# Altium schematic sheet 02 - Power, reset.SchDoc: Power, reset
size A3; PageSetup: Record=PageOptions¦CenterHorizontal=True¦CenterVertical=True¦PrintScale=0.70¦XCorrection=1.00¦YCorrection=1.00¦PrintKind=0¦BorderSize=5000000¦LeftOffset=0¦BottomOffset=0¦Orientation=2¦PaperLength=4200¦PaperWidth=2970¦Scale=100¦PaperSource=7¦PrintQuality=600¦MediaType=1¦DitherType=10¦PaperKind=A4¦PrintScaleMode=1; Author: Juan Anzola; SheetNumber: 2; SheetTotal: 20
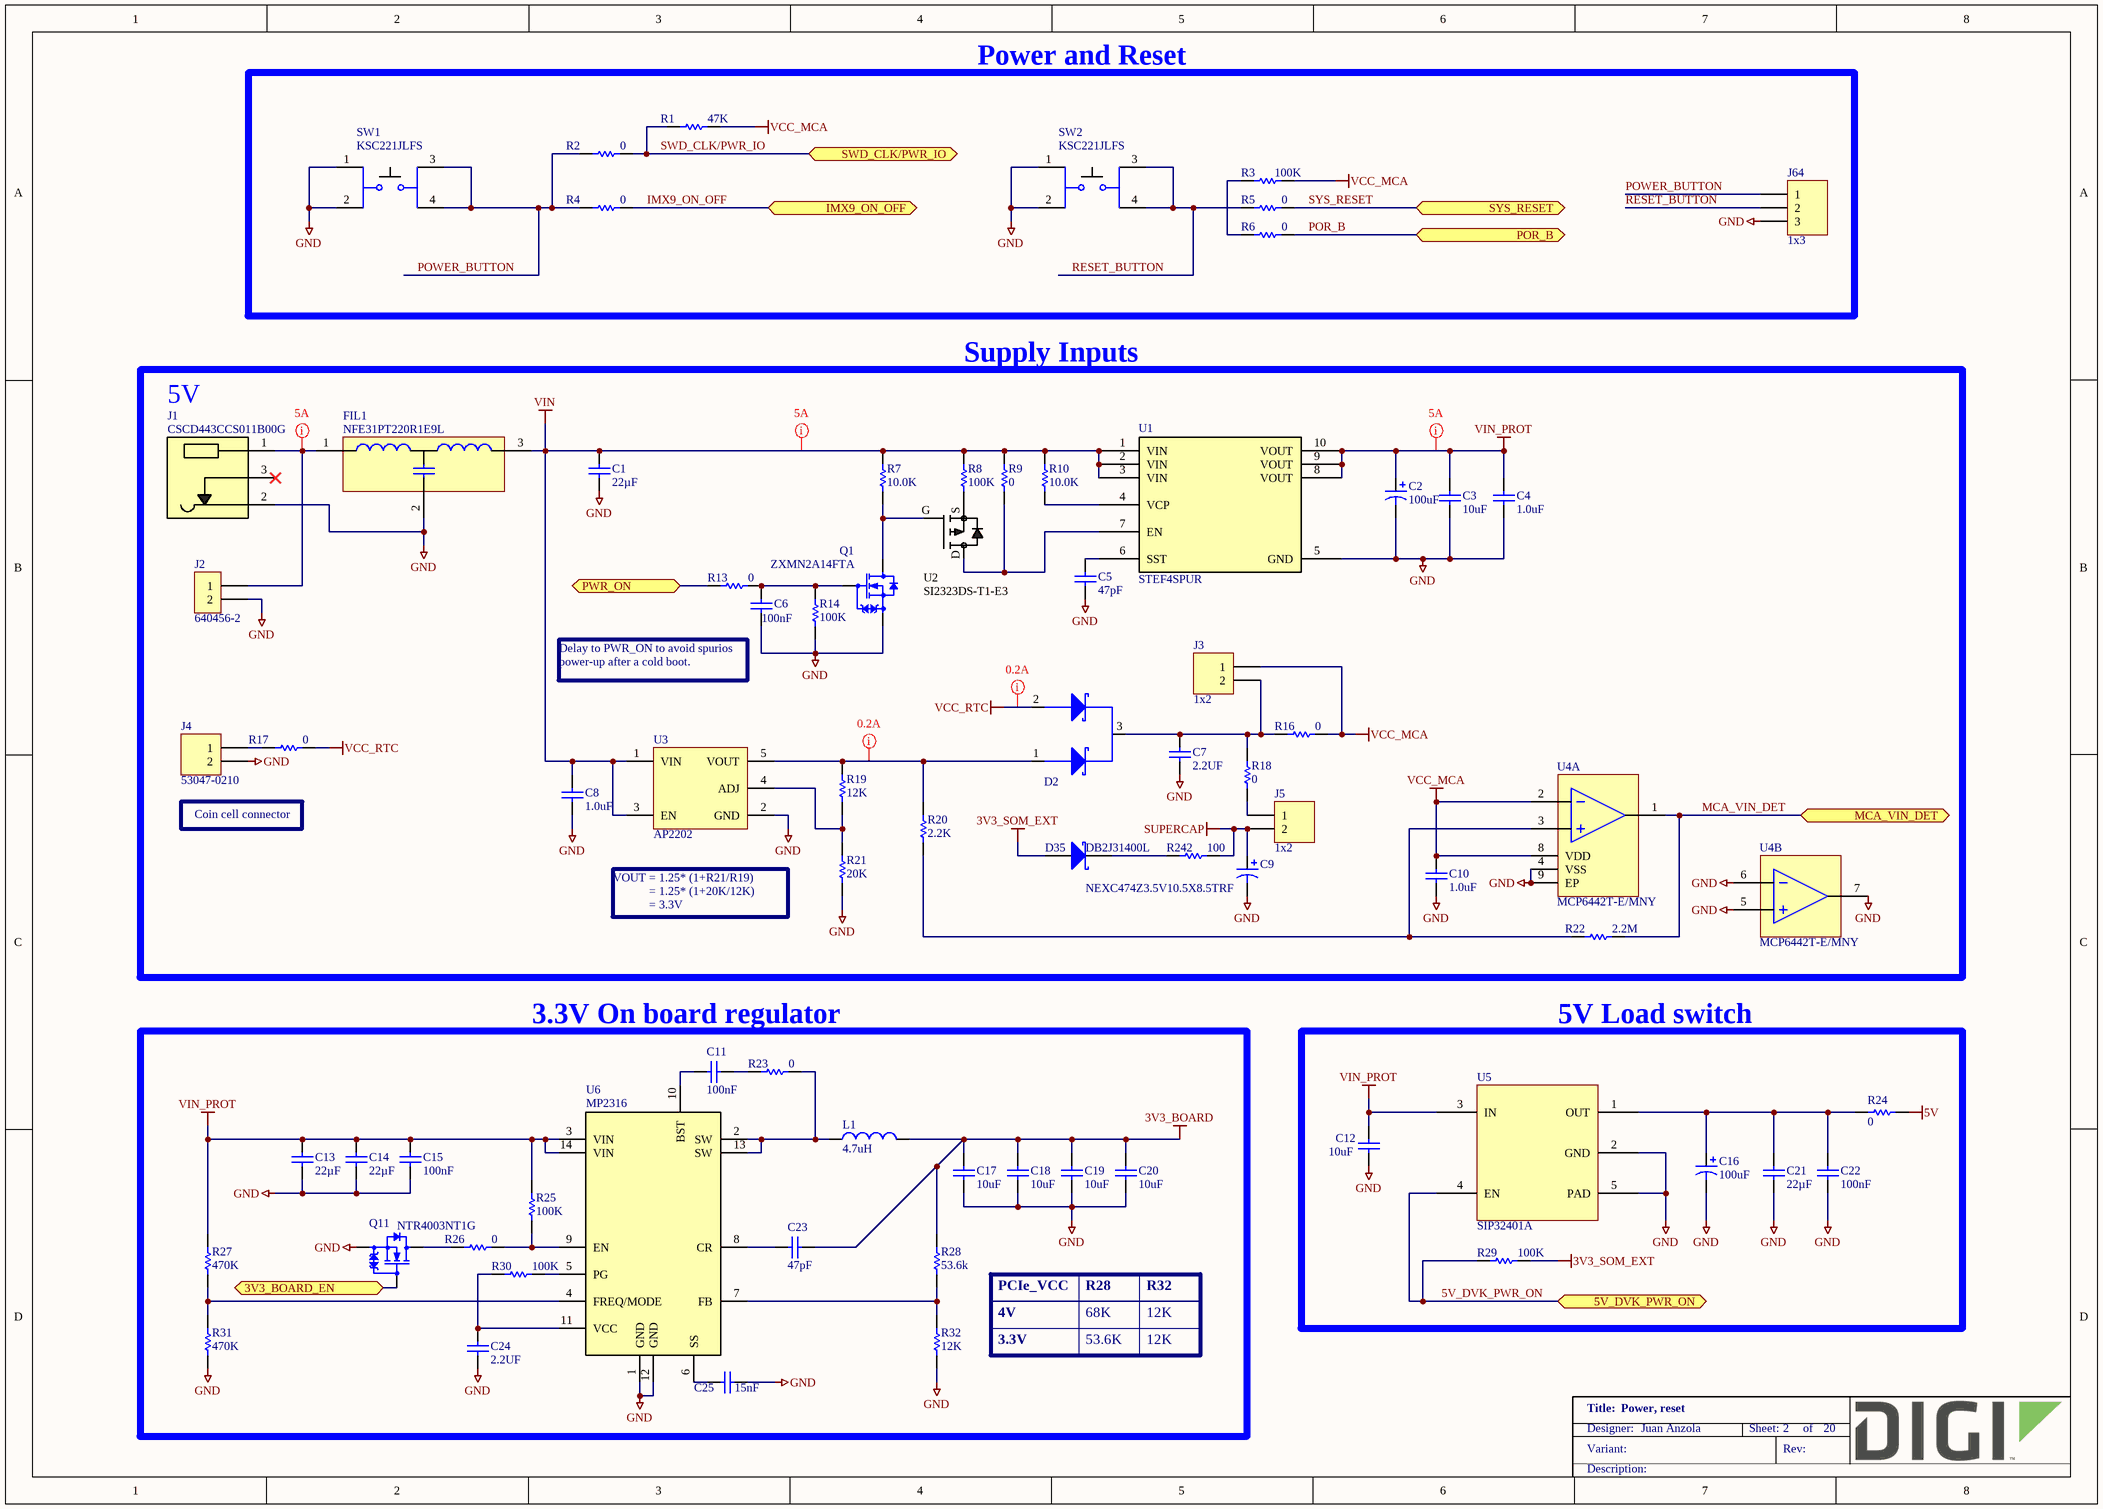
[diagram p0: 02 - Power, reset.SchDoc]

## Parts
C1  22µF  [CAPC1608X90N]
C2  100uF  [CAPMP3216X120N]
C3  10uF  [CAPC1005X55N]
C4  1.0uF  [CAPC1005X55N]
C5  47pF  [CAPC1005X55N]
C6  100nF  [CAPC1005X55N]
C7  2.2UF  [CAPC1608X90N]
C8  1.0uF  [CAPC1005X55N]
C9  NEXC474Z3.5V10.5X8.5TRF  [NEXC474Z3.5V10.5X8.5TRF]
C10  1.0uF  [CAPC1005X55N]
C11  100nF  [CAPC1005X55N]
C12  10uF  [CAPC1005X55N]
C13  22µF  [CAPC1608X90N]
C14  22µF  [CAPC1608X90N]
C15  100nF  [CAPC1005X55N]
C16  100uF  [CAPMP3216X120N]
C17  10uF  [CAPC2013X135N]
C18  10uF  [CAPC2013X135N]
C19  10uF  [CAPC2013X135N]
C20  10uF  [CAPC2013X135N]
C21  22µF  [CAPC1608X90N]
C22  100nF  [CAPC1005X55N]
C23  47pF  [CAPC1005X55N]
C24  2.2UF  [CAPC1608X90N]
C25  15nF  [CAPC1005X55N]
D2  BAT54CWT1G  [SOT65P210X100-3AN]  (value not drawn)
D35  DB2J31400L  [SODFL2513X80N]
FIL1  NFE31PT220R1E9L  [FIL_NFE31P]
J1  CSCD443CCS011B00G  [conn_CSCD443CCS011B00G]
J2  640456-2  [TE_640456-2]
J3  1x2  [FCI_68002-102HLF]
J4  Manufacturer_Part_Number: 53047-0210  [MOLEX_53047-0210_Flex]  (hidden comment: 1x2P)
J5  1x2  [FCI_68002-102HLF]
J64  1x3  [SAMTEC_TSW-103-07-G-S]
L1  4.7uH  [IND_DG6045C]
Q1  ZXMN2A14FTA  [SOT95P240X110_GSD-3N]
Q11  NTR4003NT1G  [SOT95P240X110_GSD-3N]
R1  47K  [RESC1005X40N]
R2  0  [RESC1005X40N]
R3  100K  [RESC1005X40N]
R4  0  [RESC1005X40N]
R5  0  [RESC1005X40N]
R6  0  [RESC1005X40N]
R7  10.0K  [RESC1005X40N]
R8  100K  [RESC1005X40N]
R9  0  [RESC1005X40N]
R10  10.0K  [RESC1005X40N]
R13  0  [RESC1005X40N]
R14  100K  [RESC1005X40N]
R16  0  [RESC1609X55N]
R17  0  [RESC1609X55N]
R18  0  [RESC1005X40N]
R19  12K  [RESC1609X55N]
R20  2.2K  [RESC1005X40N]
R21  20K  [RESC1609X55N]
R22  2.2M  [RESC0603X28N]
R23  0  [RESC1609X55N]
R24  0  [RESC1609X55N]
R25  100K  [RESC1005X40N]
R26  0  [RESC1005X40N]
R27  470K  [RESC1005X40N]
R28  53.6k  [RESC1609X55N]
R29  100K  [RESC1005X40N]
R30  100K  [RESC1005X40N]
R31  470K  [RESC1005X40N]
R32  12K  [RESC1609X55N]
R242  100  [RESC1005X40N]
SW1  KSC221JLFS  [SW_KSC221J]
SW2  KSC221JLFS  [SW_KSC221J]
U1  STEF4SPUR  [SON50P300X300X80-11T164X238N]
U2  SI2323DS-T1-E3  [SOT95P240X110_GSD-3N]
U3  AP2202  [SOT95P280X145-5N]
U4  MCP6442T-E/MNY  [SON50P300X200X80-9N]  (parts A,B of 2)
U5  SIP32401A  [SON50P120X160X60-5T55X91N]
U6  MP2316  [QFN_MPS_MP2316]

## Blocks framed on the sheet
Power and Reset: J64 R1-R6 SW1 SW2
Supply Inputs: C1-C10 D2 D35 FIL1 J1-J5 Q1 R7-R10 R13 R14 R16-R22 R242 U1-U4
3.3V On board regulator: C11 C13-C15 C17-C20 C23-C25 L1 Q11 R23 R25-R28 R30-R32 U6
5V Load switch: C12 C16 C21 C22 R24 R29 U5

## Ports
3V3_BOARD_EN (bidir), 5V_DVK_PWR_ON (bidir), IMX9_ON_OFF (bidir), MCA_VIN_DET (bidir), POR_B (bidir), PWR_ON (bidir), SWD_CLK/PWR_IO (bidir), SYS_RESET (bidir)

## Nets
3V3_BOARD: C17.2 C18.2 C19.2 C20.2 C23.2 L1.2 R28.2
3V3_SOM_EXT: D35.A R29.2
5V: R24.2
GND: C1.1 C2.2 C3.1 C4.1 C5.1 C6.2 C7.1 C8.1 C9.2 C10.2 C12.1 C13.1 C14.1 C15.1 C16.2 C17.1 C18.1 C19.1 C20.1 C21.1 C22.1 C24.1 C25.1 FIL1.2 J1.2 J2.2 J4.2 J64.3 Q1.S Q11.S R14.2 R21.1 R31.1 R32.1 SW1.1 SW1.2 SW2.1 SW2.2 U1.5(GND) U3.2(GND) U4.4(VSS) U4.5(VINB+) U4.6(VINB-) U4.7(VOUTB) U4.9(EP) U5.2(GND) U5.5(PAD) U6.1(GND) U6.12(GND)
SUPERCAP: C9.1 J5.2 R242.1
VCC_MCA: C10.1 J3.1 R1.2 R3.2 R16.2 U4.2(VIN-) U4.8(VDD)
VCC_RTC: D2.2 R17.2
VIN: C1.2 C8.2 FIL1.3(GND) R7.2 R8.2 R9.2 R10.2 U1.1(VIN) U1.2(VIN) U1.3(VIN) U3.1(VIN) U3.3(EN)
VIN_PROT: C2.1 C3.2 C4.2 C12.2 C13.2 C14.2 C15.2 R25.2 R27.2 U1.8(VOUT) U1.9(VOUT) U1.10(VOUT) U5.3(IN) U6.3(VIN) U6.14(VIN)
3V3_BOARD_EN: Q11.G ; port 3V3_BOARD_EN
5V_DVK_PWR_ON: R29.1 U5.4(EN) ; port 5V_DVK_PWR_ON
IMX9_ON_OFF: R4.2 ; port IMX9_ON_OFF
MCA_VIN_DET: R22.2 U4.1(VOUT) ; port MCA_VIN_DET
POR_B: R6.2 ; port POR_B
POWER_BUTTON: J64.1 R2.1 R4.1 SW1.3 SW1.4
PWR_ON: R13.1 ; port PWR_ON
RESET_BUTTON: J64.2 R5.1 SW2.3 SW2.4
SWD_CLK/PWR_IO: R1.1 R2.2 ; port SWD_CLK/PWR_IO
SYS_RESET: R5.2 ; port SYS_RESET
NetC5_2: C5.2 U1.6(SST)
NetC6_1: C6.1 Q1.G R13.2 R14.1
NetC7_2: C7.2 D2.3 J3.2 R16.1 R18.2
NetC11_1: C11.1 U6.10(BST)
NetC11_2: C11.2 R23.1
NetC16_1: C16.1 C21.2 C22.2 R24.1 U5.1(OUT)
NetC23_1: C23.1 U6.8(CR)
NetC24_2: C24.2 R30.1 U6.11(VCC)
NetC25_2: C25.2 U6.6(SS)
NetD2_1: D2.1 R19.2 R20.2 U3.5(VOUT)
NetD35_K: D35.K R242.2
NetFIL1_1: FIL1.1(GND) J1.1 J2.1
NetJ4_1: J4.1 R17.1
NetJ5_1: J5.1 R18.1
NetL1_1: L1.1 R23.2 U6.2(SW) U6.13(SW)
NetQ1_D: Q1.D R7.1 U2.G
NetQ11_D: Q11.D R26.1
NetR3_1: R3.1 R6.1
NetR8_1: R8.1 U2.S
NetR9_1: R9.1 U1.7(EN) U2.D
NetR10_1: R10.1 U1.4(VCP)
NetR19_1: R19.1 R21.2 U3.4(ADJ)
NetR20_1: R20.1 R22.1 U4.3(VIN+)
NetR25_1: R25.1 R26.2 U6.9(EN)
NetR27_1: R27.1 R31.2 U6.4(FREQ/MODE)
NetR28_1: R28.1 R32.2 U6.7(FB)
NetR30_2: R30.2 U6.5(PG)

Not connected (* = marked no-connect by the designer): J1 3*

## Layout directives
net class 0.2A: NetD2_1, VCC_RTC
net class 5A: NetFIL1_1, VIN, VIN_PROT

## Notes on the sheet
- 5V
- (near C6) Delay to PWR_ON to avoid spurios
  power-up after a cold boot.
- Coin cell connector
- VOUT = 1.25* (1+R21/R19)
  = 1.25* (1+20K/12K)
  = 3.3V
- PCIe_VCC
- 4V
- R28
- 68K
- R32
- 12K
- 3.3V
- 53.6K

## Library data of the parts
C1 = 1000998: CAP CER 22UF 10V 20% X5R 0603; Part_Type: Capacitor; Manufacturer: Samsung; Manufacturer_Part_Number: CL10A226MP8NUNE; Manufacturer_Alt_1: TDK Corporation; Manufacturer_Alt_1_Part_Number: C1608X5R1A226M080AC; Digi_PN: 14050684; Component_Life_Cycle_State: Reviewed; Area: 2,27; Tolerance: 20
C2 C16 = 1001196: CAP TANT 100UF 6.3V 20% 1206; Part_Type: Capacitor; Manufacturer: Rohm; Manufacturer_Part_Number: TCTAL0J107M8R; Digi_PN: 14050490; Component_Life_Cycle_State: Reviewed; Area: 8.01; Project: CCWMX6_SBC board
C3 C12 = 1001168: CAP CER 10UF 10V 20% X5R 0402; Part_Type: Capacitor; Manufacturer: Samsung; Manufacturer_Part_Number: CL05A106MP5NUNC; Digi_PN: 14050689; Component_Life_Cycle_State: Reviewed; Area: 0.95; Project: CCWMX6_SBC board
C4 = 1001167: CAP CER 1UF 10V 10% X5R 0402; Part_Type: Capacitor; Manufacturer: Murata; Manufacturer_Part_Number: GRM155R61A105KE15D; Digi_PN: 14050399; Component_Life_Cycle_State: Reviewed; Area: 0,95; Project: CCWMX6_SBC board
C5 = 1000007: CAP 47pF 50V 5% NP0 0402; Part_Type: Capacitor; Manufacturer: Murata; Manufacturer_Part_Number: GRM1555C1H470JA01D; Manufacturer_Alt_1: AVX Corporation; Manufacturer_Alt_1_Part_Number: 04025A470JAT2A; Note: 14050747 is Digi No. for GE WDNU; Digi_PN: 14050309; Component_Life_Cycle_State: CAD Reviewed; Area: 0,95; Temp_Coef: C0G, NP0
C6 C22 = 1000006: CAP 100nF 16V 10% X7R 0402; Part_Type: Capacitor; Manufacturer: Murata; Manufacturer_Part_Number: GRM155R71C104KA88D; Component_Life_Cycle_State: CAD Reviewed; Area: 0.95; Project: KITT; Tolerance: 10; Digi_PN: 14050552
C7 C24 = 1001303: CAP CER 2.2UF 16V 10% X5R 0603; Part_Type: Capacitor; Manufacturer: TDK Corporation; Manufacturer_Part_Number: C1608X5R1C225K080AB; Digi_PN: 14050730; Component_Life_Cycle_State: Reviewed; Area: 2,27; Project: Pinnacle
C8 C10 = 1001167: CAP CER 1UF 10V 10% X5R 0402; Part_Type: Capacitor; Manufacturer: Murata; Manufacturer_Part_Number: GRM155R61A105KE15D; Digi_PN: 14050399; Component_Life_Cycle_State: Reviewed; Area: 0,95
C9 = 1002775: SMCAP, 0.47F 3.5V SUPERCAP 8.5x10.5x10.8mm SMT; Part_Type: Capacitor; Manufacturer: NIC; Digi_PN: 14050629; Component_Life_Cycle_State: Pending
C11 C15 = 1000006: CAP 100nF 16V 10% X7R 0402; Part_Type: Capacitor; Manufacturer: Murata; Manufacturer_Part_Number: GRM155R71C104KA88D; Digi_PN: 14050552; Component_Life_Cycle_State: CAD Reviewed; Area: 0.95; Project: KITT; Tolerance: 10
C13 C14 C21 = 1000998: CAP CER 22UF 10V 20% X5R 0603; Part_Type: Capacitor; Manufacturer: Samsung; Manufacturer_Part_Number: CL10A226MP8NUNE; Manufacturer_Alt_1: TDK Corporation; Manufacturer_Alt_1_Part_Number: C1608X5R1A226M080AC; Digi_PN: 14050684; Component_Life_Cycle_State: Reviewed; Area: 2.27; Project: ConnectCore i.MX6 module; Tolerance: 20
C17-C20 = 1000111: CAP CER 10UF 16V 10% X5R 0805; Part_Type: Capacitor; Manufacturer: Murata; Manufacturer_Part_Number: GRM21BR61C106KE15L; Digi_PN: 14050701; Component_Life_Cycle_State: Proven; Area: 3.99; Project: Adjustable Foundation; Tolerance: 10
C23 = 1000007: CAP 47pF 50V 5% NP0 0402; Part_Type: Capacitor; Manufacturer: Murata; Manufacturer_Part_Number: GRM1555C1H470JA01D; Manufacturer_Alt_1: AVX Corporation; Manufacturer_Alt_1_Part_Number: 04025A470JAT2A; Note: 14050747 is Digi No. for GE WDNU; Digi_PN: 14050309; Component_Life_Cycle_State: CAD Reviewed; Area: 0.95; Project: KITT; Temp_Coef: C0G, NP0
C25 = 1000512: CAP CER 0.015UF 16V 10% X7R 0402; Part_Type: Capacitor; Manufacturer: Murata; Manufacturer_Part_Number: GRM155R71C153KA01D; Digi_PN: 14050713; Component_Life_Cycle_State: CAD Reviewed; Area: 0.95; Project: Cellular Proof of Concept
D2 = 1000794: DIODE SCHOTTKY 30V 200MA SOT323; Part Number: SDS1920004; Manufacturer: Fairchild Semiconductor; Manufacturer Alt 1: none; Manufacturer Part Num: 0082610201; Part_Type: Diodes; Digi_PN: 17050561; Component_Life_Cycle_State: CAD Reviewed; Area: 7,68; Project: SmartMeter2
D35 = 1002592: DIODE SCHOTTKY 30V 30MA SMINI2; Part_Type: Diodes; Manufacturer: Panasonic - ECG; Digi_PN: 17000142; Component_Life_Cycle_State: Reviewed; Area: 6,06
FIL1 = 1002745: FILTER LC(T) 22PF SMD; Manufacturer: Murata; Digi_PN: 21000602; Component_Life_Cycle_State: Created; Area: 15
J1 = 1001105: DC Power Jack; Part_Type: Connector; Manufacturer: Bobbintron Electrical Corp; Digi_PN: 18000302; Component_Life_Cycle_State: Reviewed; Area: 137; Project: CCWMX6_SBC board
J2 = 1002003: CONN HEADER VERT 2POS .100 TIN; Part_Type: Connector; Manufacturer: TE Connectivity; Digi_PN: 18050128; Component_Life_Cycle_State: Created; Area: 29,05; Project: iMX6UL+PMIC
J3 J5 = 1001128: CONN HEADER 2POS .100" SGL GOLD; Part_Type: Connector; Manufacturer: Samtec; Manufacturer_Part_Number: TSW-102-07-G-S; Digi_PN: 00120002; Component_Life_Cycle_State: Reviewed; Area: 12,9032
J4 = 1001136: CONN HEADER 2POS 1.25MM VERT TIN; Part_Type: Connector; Manufacturer: Molex; Component_Life_Cycle_State: Reviewed; Area: 13.6; Project: CCWMX6_SBC board; Digi_PN: 18050343
J64 = 1002832: CONN HEADER 3POS .100" SGL GOLD; Part_Type: Connector; Manufacturer: Samtec; Manufacturer_Part_Number: TSW-103-07-G-S; Digi_PN: 00120003; Component_Life_Cycle_State: Pending; Area: 19,3548
L1 = 1002747: FIXED IND 4.7UH 4.5A 27.6 MOHM; Manufacturer: Murata; Manufacturer_Part_Number: 1255AY-4R7M=P3; Digi_PN: 21000603; Component_Life_Cycle_State: Reviewed; Area: 49
Q1 = 1002855: MOSFET N-CH 20V 3.4A SOT23-3; Part_Type: Transistor; Manufacturer: Diodes, Inc.; Digi_PN: 17000304; Component_Life_Cycle_State: Pending
Q11 = 1000306: MOSFET N-CH 30V 500MA SOT-23; Part_Type: Transistor; Manufacturer: On Semiconductor; Digi_PN: 17050809; Component_Life_Cycle_State: Proven; Area: 10,92
R1 = 1001155: RES 47.0K OHM 1/16W 1% 0402 SMD; Part_Type: Resistor; Manufacturer: Vishay Dale; Manufacturer_Part_Number: CRCW040247K0FKED; Digi_PN: 13050646; Component_Life_Cycle_State: Reviewed; Area: 0.95; Project: CCWMX6_SBC board
R2 R4-R6 R13 R26 = 1000076: RES 0.0 OHM 1/10W 0402 SMD; Part_Type: Resistor; Manufacturer: Panasonic - ECG; Manufacturer_Part_Number: ERJ-2GE0R00X; Component_Life_Cycle_State: Proven; Area: 0.95; Project: Adjustable Foundation; Power_WV_SRF: 10; Digi_PN: 13050387
R3 = 1000480: RES 100K OHM 1/10W 1% 0402 SMD; Part_Type: Resistor; Manufacturer: Panasonic - ECG; Manufacturer_Part_Number: ERJ-2RKF1003X; Digi_PN: 13051063; Component_Life_Cycle_State: CAD Reviewed; Area: 0,95; Project: KITT; Power_WV_SRF: 100
R7 R10 = 1000537: RES 10.0K OHM 1/10W 1% 0402 SMD; Part_Type: Resistor; Manufacturer: Panasonic - ECG; Manufacturer_Part_Number: ERJ-2RKF1002X; Component_Life_Cycle_State: CAD Reviewed; Area: 0.95; Project: KITT; Power_WV_SRF: 100; Digi_PN: 13051084
R8 = 1000480: RES 100K OHM 1/10W 1% 0402 SMD; Part_Type: Resistor; Manufacturer: Panasonic - ECG; Manufacturer_Part_Number: ERJ-2RKF1003X; Digi_PN: 13051063; Component_Life_Cycle_State: CAD Reviewed; Area: 0,95; Power_WV_SRF: 100
R9 R18 = 1000076: RES 0.0 OHM 1/10W 0402 SMD; Part_Type: Resistor; Manufacturer: Panasonic - ECG; Manufacturer_Part_Number: ERJ-2GE0R00X; Digi_PN: 13050387; Component_Life_Cycle_State: Proven; Area: 0,95; Power_WV_SRF: 10
R14 R25 R29 R30 = 1000480: RES 100K OHM 1/10W 1% 0402 SMD; Part_Type: Resistor; Manufacturer: Panasonic - ECG; Manufacturer_Part_Number: ERJ-2RKF1003X; Digi_PN: 13051063; Component_Life_Cycle_State: CAD Reviewed; Area: 0.95; Project: KITT; Power_WV_SRF: 100
R16 R17 R23 = 1000208: RES 0.0 OHM 1/10W 0603; Part_Type: Resistor; Manufacturer: Panasonic - ECG; Manufacturer_Part_Number: ERJ-3GEY0R00V; Note: 13051103 = Digi No. for GE WDNU; Digi_PN: 13050568; Component_Life_Cycle_State: Reviewed; Area: 2,5; Voltage: 75V
R19 = 1001200: RES 12.0K OHM 1/10W 1% 0603 SMD; Part_Type: Resistor; Manufacturer: Yageo; Manufacturer_Part_Number: RC0603FR-0712KL; Digi_PN: 13050531; Component_Life_Cycle_State: Reviewed; Area: 2,5; Project: LuCoV2; Power_WV_SRF: 100; Tolerance: 1
R20 = 1001156: RES 2.20K OHM 1/16W 1% 0402 SMD; Part_Type: Resistor; Manufacturer: Yageo; Manufacturer_Part_Number: RC0402FR-072K2L; Note: 13051099 = Digi No. for GE WDNU; Digi_PN: 13050699; Component_Life_Cycle_State: Reviewed; Area: 0,95
R21 = 1000142: RES 20K OHM 1/10W 5% 0603 SMD; Part_Type: Resistor; Manufacturer: Panasonic - ECG; Manufacturer_Part_Number: ERJ-3GEYJ203V; Digi_PN: 13050013; Component_Life_Cycle_State: Reviewed; Area: 2,5; Project: Adjustable Foundation; Power_WV_SRF: 100; Tolerance: 5
R22 = 1000980: RES 2.2M OHM 1/20W 5% 0201 SMD; Part_Type: Resistor; Manufacturer: Rohm; Manufacturer_Part_Number: MCR006YZPJ225; Manufacturer_Alt_1: Panasonic - ECG; Manufacturer_Alt_1_Part_Number: ERJ-1GEJ225C; Digi_PN: 13050884; Component_Life_Cycle_State: Reviewed; Area: 1,73; Power_WV_SRF: 50; Tolerance: 5
R24 = 1000208: RES 0.0 OHM 1/10W 0603; Part_Type: Resistor; Manufacturer: Panasonic - ECG; Manufacturer_Part_Number: ERJ-3GEY0R00V; Note: 13051103 = Digi No. for GE WDNU; Digi_PN: 13050568; Component_Life_Cycle_State: Reviewed; Area: 2.5; Project: Adjustable Foundation; Voltage: 75V
R27 R31 = 1000701: RES 470K OHM 1/10W 1% 0402 SMD; Part_Type: Resistor; Manufacturer: Panasonic - ECG; Manufacturer_Part_Number: ERJ-2RKF4703X; Digi_PN: 13051092; Component_Life_Cycle_State: CAD Reviewed; Area: 0.95; Project: KITT; Power_WV_SRF: 100
R28 = 1001518: RES 53.6K OHM 1/10W 1% 0603 SMD; Part_Type: Resistor; Manufacturer: Panasonic - ECG; Manufacturer_Part_Number: ERJ-3EKF5362V; Digi_PN: 13051064; Component_Life_Cycle_State: Reviewed; Area: 2.5; Project: WDNU-II
R32 = 1001200: RES 12.0K OHM 1/10W 1% 0603 SMD; Part_Type: Resistor; Manufacturer: Yageo; Manufacturer_Part_Number: RC0603FR-0712KL; Digi_PN: 13050531; Component_Life_Cycle_State: Reviewed; Area: 2.5; Project: LuCoV2; Power_WV_SRF: 100; Tolerance: 1
R242 = 1000467: RES 100 OHM 1/10W 1% 0402 SMD; Part_Type: Resistor; Manufacturer: Panasonic - ECG; Manufacturer_Part_Number: ERJ-2RKF1000X; Digi_PN: 13051087; Component_Life_Cycle_State: CAD Reviewed; Area: 0,95
SW1 SW2 = 1001124: SWITCH TACTILE SPST-NO 0.05A 32V; Manufacturer: ITT; Digi_PN: 22000059; Component_Life_Cycle_State: Reviewed; Area: 37; Project: CCWMX6_SBC board; Note: 22000295 = Digi No. for GE WDNU
U1 = 1002744: IC ELECTRONIC FUSE 10VFDFPN; Manufacturer: STMicroelectronics; Digi_PN: 16000208; Component_Life_Cycle_State: Created; Area: 14,77
U2 = 1001163: MOSFET P-CH 20V 3.7A SOT23-3; Part_Type: IC; Manufacturer: Vishay Siliconix; Digi_PN: 17050358; Component_Life_Cycle_State: Reviewed; Area: 10.92; Project: CCWMX6_SBC board
U3 = 1001979: IC REG LDO ADJ 0.15A SOT25; Part_Type: Regulator; Manufacturer: Diodes, Inc.; Manufacturer_Part_Number: AP2202K-ADJTRG1; Digi_PN: 17050874; Component_Life_Cycle_State: Created; Area: 8,9; Project: iMX6UL+PMIC
U4 = 1000217: IC OPAMP DUAL 1.6V 9KHZ 8TDFN; Manufacturer: Microchip; Digi_PN: 16000212; Component_Life_Cycle_State: Reviewed; Area: 7,4
U5 = 1001857: IC SW W/CTRL SLEW RATE 4TDFN; Manufacturer: Vishay Siliconix; Manufacturer_Part_Number: SIP32401ADNP-T1GE4; Component_Life_Cycle_State: Reviewed; Area: 4.93; Project: CCWMX6_SBC board; Digi_PN: 16052004
U6 = 1001907: IC REG BUCK ADJ 3A SYNC; Manufacturer: Linear Technology; Manufacturer_Part_Number: MP2316GD; Digi_PN: 17050862; Component_Life_Cycle_State: Reviewed; Area: 9.375; Project: CCWMX6_SBC board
